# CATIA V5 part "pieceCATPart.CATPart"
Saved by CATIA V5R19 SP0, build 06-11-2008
Part number: Part4.1
Bounding box of the stored display mesh (mm): x 0 to 20, y -18.982 to 58.153, z -35.517 to -11.523
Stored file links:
  D:\thinkmotion-MPB\Dropbox\CIAO82010_JCF\BOUCHEFRA\580-bouchefra\pieceCATPart.CATPart
  D:\thinkmotion-MPB\Dropbox\CIAO82010_JCF\BOUCHEFRA\580-bouchefra\piece3.CATPart
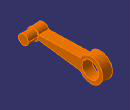
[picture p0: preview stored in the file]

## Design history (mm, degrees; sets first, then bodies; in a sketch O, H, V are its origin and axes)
Body1 (main body)
  Sketch1 on yz-plane, origin (0, 0, 0), H (0, 1, 0), V (0, 0, 1)
    arc A1 centre (46.1554, -23.5174) radius 12 from (35.5462, -17.9099) to (35.7984, -29.5782) cw
    point P1 (35.7984, -29.5782)
    point P2 (35.7984, -29.5782)
    arc A2 centre (-12.9872, -21.0943) radius 6 from (-7.2989, -19.1854) to (-7.6335, -23.8033) ccw
    line L1 (35.5462, -17.9099) -> (-7.2989, -19.1854)
    line L2 (35.7984, -29.5782) -> (-7.6335, -23.8033)
    radius A1 = 12
    coincidence: P1 A1, P2 P1
  Pad1: profile Sketch1, direction (1, 0, 0), length 10
  Sketch2 on end face of Pad1, origin (10, 43.3186, -19.041), H (0, 1, 0), V (0, 0, 1)
    point P1 (2.3429, -4.6026)
  Hole1: placed by Sketch2, at (10, 45.6615, -23.6437) direction (-1, 0, 0), diameter 17, through (limit type 3)
  Sketch3 on end face of Pad1, origin (10, 0, 0), H (0, 1, 0), V (0, 0, 1)
    circle A1 centre (-13.1165, -21.1723) radius 5
    radius A1 = 5
  Pad2: profile Sketch3, direction (1, 0, 0), length 10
